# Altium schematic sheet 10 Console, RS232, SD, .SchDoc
size 420 x 297 mm; DocumentNumber: 10; SheetNumber: 10; SheetTotal: 12
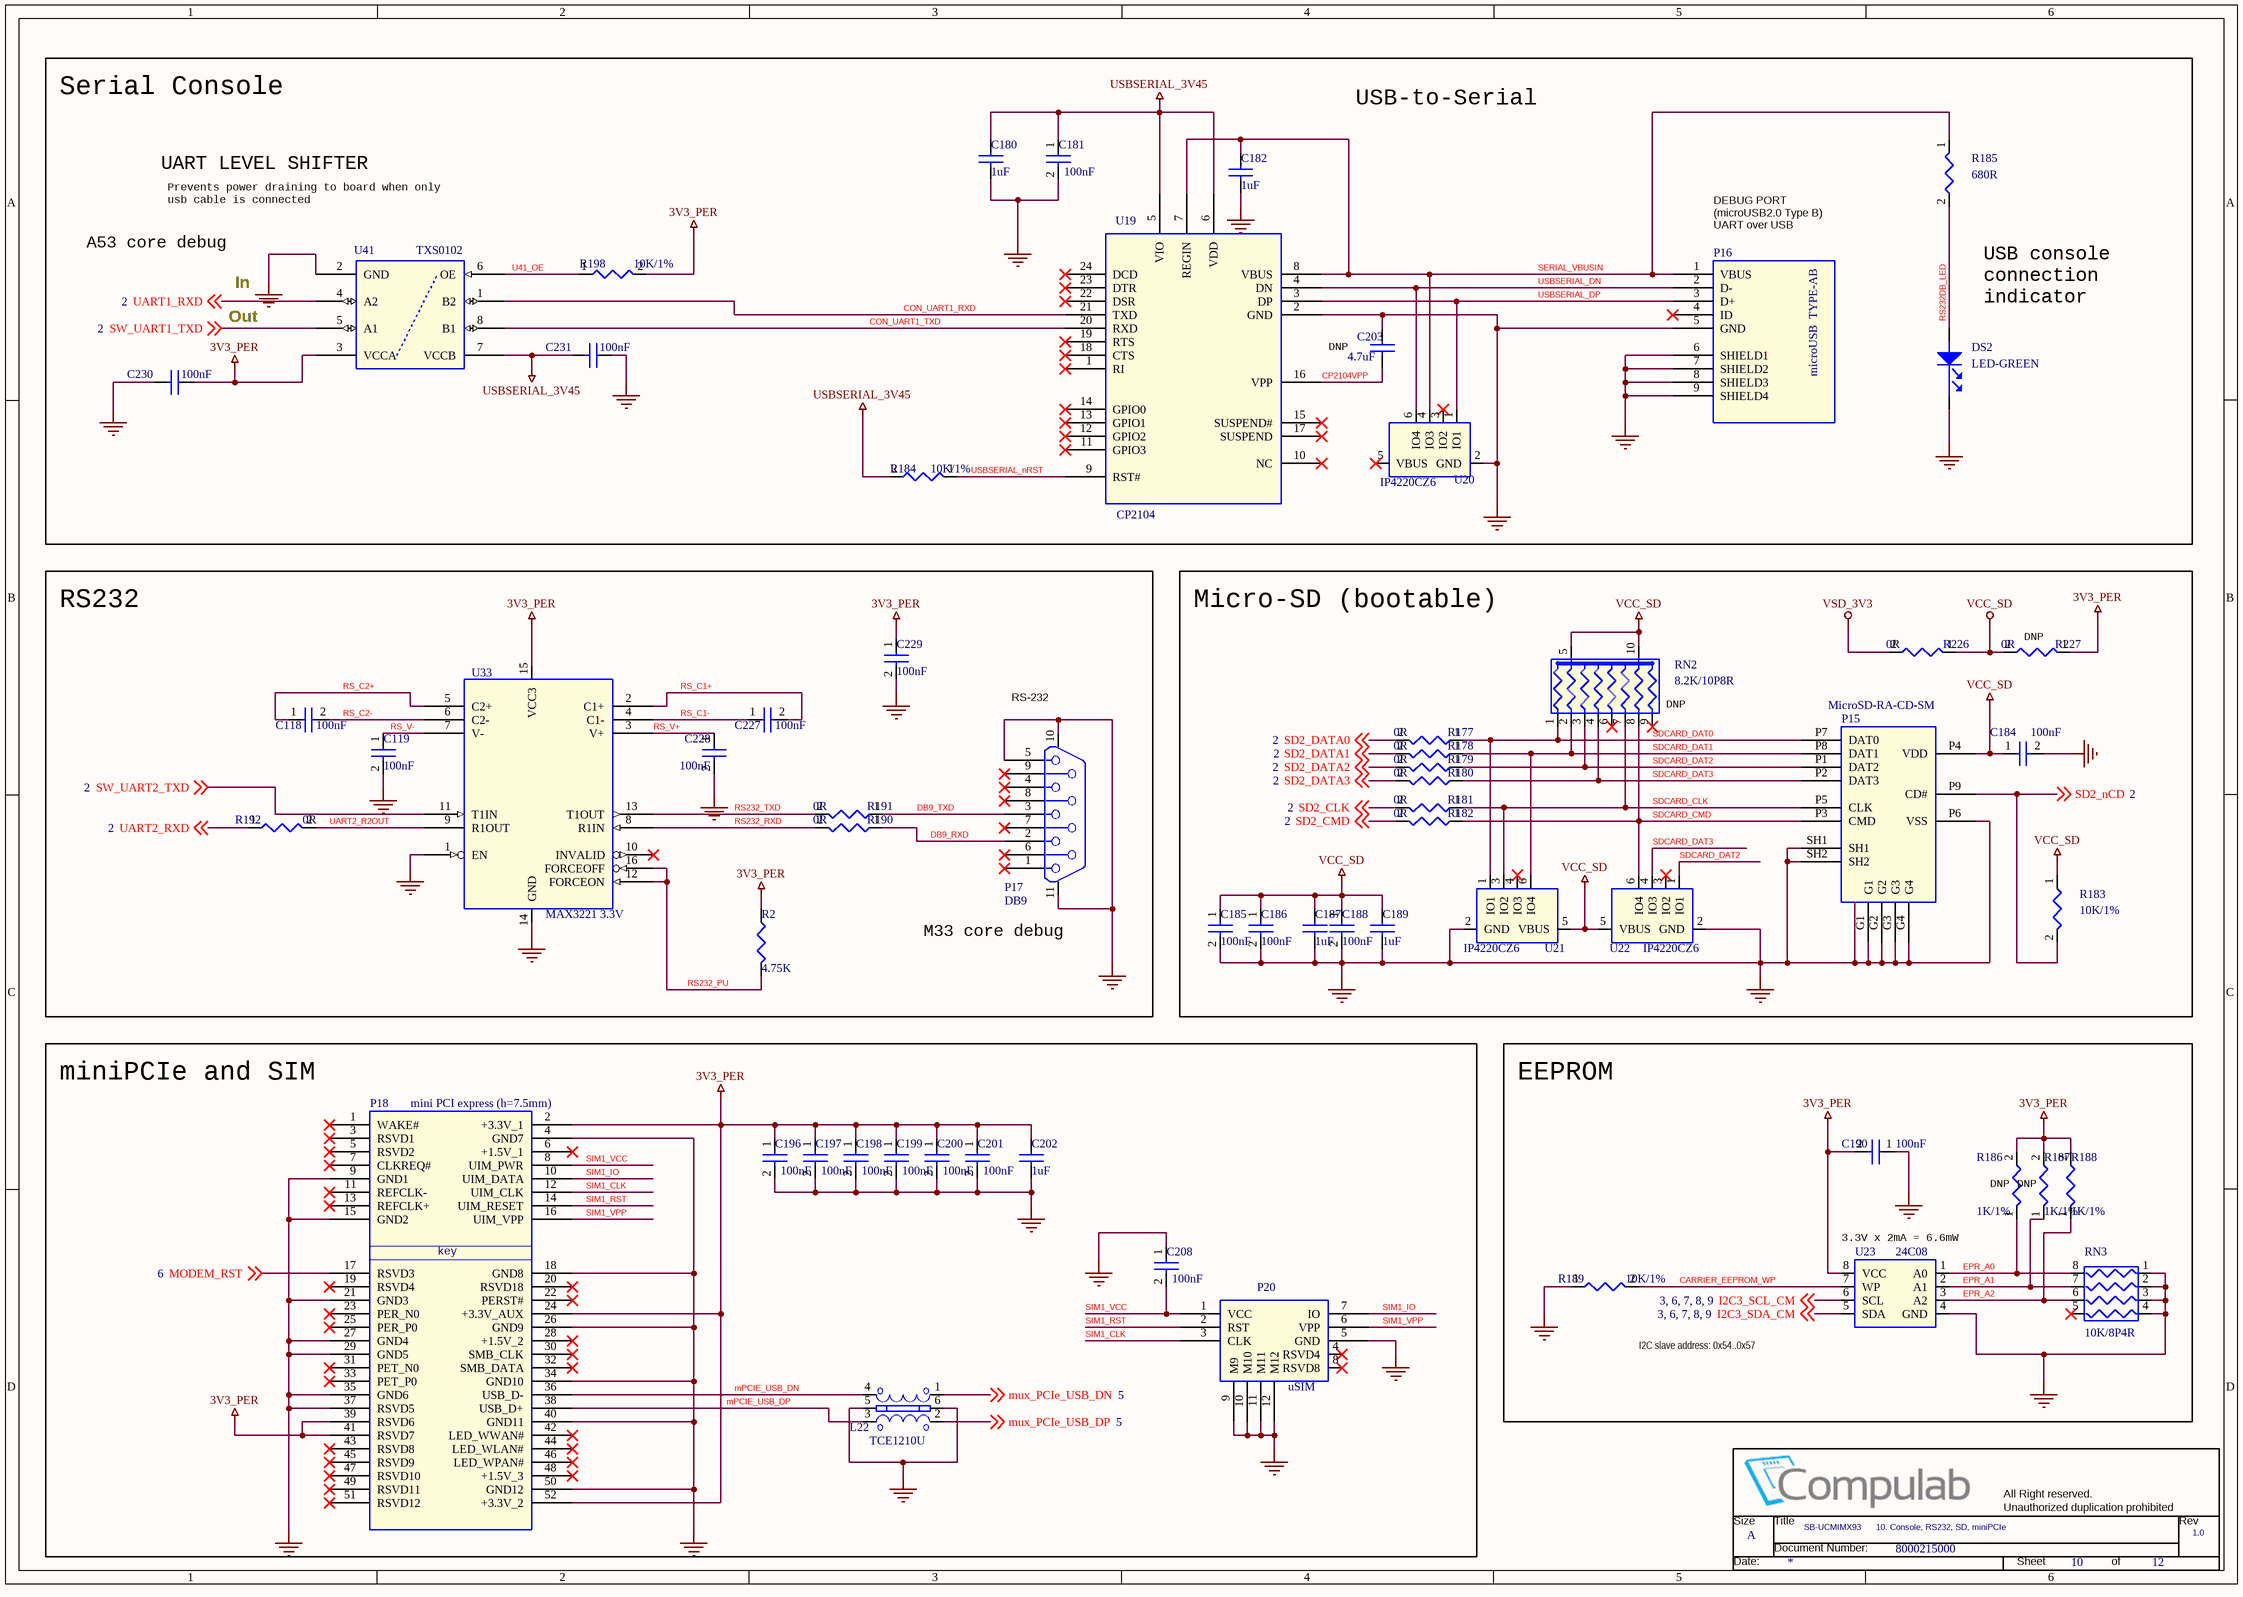
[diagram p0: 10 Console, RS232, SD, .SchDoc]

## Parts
*  Title: SB-UCMIMX93      10. Console, RS232, SD, miniPCIe  Doc: 8000215000  RevCode: 1.0  Page Size: A  Page Number: 10  Page Count: 12  (hidden comment: CompuLabTitleBlk)  (graphical)
C118  100nF  [RC0402]
C119  100nF  [RC0402]
C180  1uF  [RC0402]
C181  100nF  [RC0402]
C182  1uF  [RC0402]
C184  100nF  [RC0402]
C185  100nF  [RC0402]
C186  100nF  [RC0402]
C187  1uF  [RC0402]
C188  100nF  [RC0402]
C189  1uF  [RC0402]
C190  100nF  [RC0402]
C196  100nF  [RC0402]
C197  100nF  [RC0402]
C198  100nF  [RC0402]
C199  100nF  [RC0402]
C200  100nF  [RC0402]
C201  100nF  [RC0402]
C202  1uF  [RC0402]
C203  4.7uF  [C0603-08]
C208  100nF  [RC0402]
C227  100nF  [RC0402]
C228  100nF  [RC0402]
C229  100nF  [RC0402]
C230  100nF  [RC0402]
C231  100nF  [RC0402]
DS2  LED-GREEN  [LED-1206]
L22  TCE1210U  [EMI1012-ESD]
P15  MicroSD-RA-CD-SM  [MicroSD-RA-CD-SM]
P16  microUSB  TYPE-AB  [MICRO-USB-AB-RA-SM]
P17  DB9  [DB9RATH]
P18  mini PCI express (h=7.5mm)  [MINIPCIE-4]
P20  uSIM  [SKT-MicroSIM6-SM]
R2  4.75K  [RC0402]
R177  0R  [RC0402]
R178  0R  [RC0402]
R179  0R  [RC0402]
R180  0R  [RC0402]
R181  0R  [RC0402]
R182  0R  [RC0402]
R183  10K/1%  [RC0402]
R184  10K/1%  [RC0402]
R185  680R  [RC0402]
R186  1K/1%  [RC0402]
R187  1K/1%  [RC0402]
R188  1K/1%  [RC0402]
R189  10K/1%  [RC0402]
R190  0R  [RC0402]
R191  0R  [RC0402]
R192  0R  [RC0402]
R198  10K/1%  [RC0402]
R226  0R  [RC0402]
R227  0R  [RC0402]
RN2  8.2K/10P8R  [RESNET10P1206]
RN3  10K/8P4R  [RESNET8P0805]
U19  CP2104  [MO-220VGGD-8]
U20  IP4220CZ6  [SOT23-6L-H1]
U21  IP4220CZ6  [SOT23-6L]
U22  IP4220CZ6  [SOT23-6L]
U23  24C08  [MO-229VCED-2]
U33  MAX3221 3.3V  [SSOP-16]
U41  TXS0102  [MO-187DA-8]

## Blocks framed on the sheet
Serial Console: C180-C182 C203 C230 C231 DS2 P16 R184 R185 R198 U19 U20 U41
RS232: C118 C119 C227-C229 P17 R2 R190-R192 U33
Micro-SD (bootable): C184-C189 P15 R177-R183 R226 R227 RN2 U21 U22
miniPCIe and SIM: C196-C202 C208 L22 P18 P20
EEPROM: C190 R186-R189 RN3 U23

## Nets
3V3_PER: C190.2 C196.1 C197.1 C198.1 C199.1 C200.1 C201.1 C202.1 C229.1 C230.1 P18.2(+3.3V_1) P18.24(+3.3V_AUX) P18.39(RSVD6) P18.41(RSVD7) P18.52(+3.3V_2) R2.1 R186.2 R187.2 R188.2 R198.2 R227.1 U23.8(VCC) U33.15(VCC3) U41.3(VCCA)
GND: C119.2 C180.2 C181.2 C182.2 C184.2 C185.2 C186.2 C187.2 C188.2 C189.2 C190.1 C196.2 C197.2 C198.2 C199.2 C200.2 C201.2 C202.2 C203.2 C208.1 C228.2 C229.2 C230.2 C231.1 DS2.CATHODE L22.5(GND) L22.6(GND) P15.G1 P15.G2 P15.G3 P15.G4 P15.P6(VSS) P15.SH1 P15.SH2 P16.5(GND) P16.6(SHIELD1) P16.7(SHIELD2) P16.8(SHIELD3) P16.9(SHIELD4) P17.5 P17.10(BRACKET) P17.11(BRACKET) P18.4(GND7) P18.9(GND1) P18.15(GND2) P18.18(GND8) P18.21(GND3) P18.26(GND9) P18.27(GND4) P18.29(GND5) P18.34(GND10) P18.35(GND6) P18.37(RSVD5) P18.40(GND11) P18.50(GND12) P20.5(GND) P20.9(M9) P20.10(M10) P20.11(M11) P20.12(M12) R189.1 RN3.1(RA1) RN3.2(RB1) RN3.3(RC1) RN3.4(RD1) U19.2(GND) U20.2(GND) U21.2(GND) U22.2(GND) U23.4(GND) U33.1(EN) U33.14(GND) U41.2(GND)
USBSERIAL_3V45: C180.1 C181.1 C231.2 R184.2 U19.5(VIO) U19.6(VDD) U41.7(VCCB)
VCC_SD: C184.1 C185.1 C186.1 C187.1 C188.1 C189.1 P15.P4(VDD) R183.1 R226.1 R227.2 RN2.5(COM1) RN2.10(COM2) U21.5(VBUS) U22.5(VBUS)
VSD_3V3: R226.2
CARRIER_EEPROM_WP: R189.2 U23.7(WP)
CON_UART1_RXD: U19.21(TXD) U41.1(B2)
CON_UART1_TXD: U19.20(RXD) U41.8(B1)
CP2104VPP: C203.1 U19.16(VPP)
DB9_RXD: P17.2 R190.1
DB9_TXD: P17.3 R191.1
EPR_A0: R186.1 RN3.8(RA2) U23.1(A0)
EPR_A1: R187.1 RN3.7(RB2) U23.2(A1)
EPR_A2: R188.1 RN3.6(RC2) U23.3(A2)
I2C3_SCL_CM: U23.6(SCL) ; off-sheet I2C3_SCL_CM
I2C3_SDA_CM: U23.5(SDA) ; off-sheet I2C3_SDA_CM
MODEM_RST: P18.17(RSVD3) ; off-sheet MODEM_RST
mPCIE_USB_DN: L22.4 P18.36(USB_D-)
mPCIE_USB_DP: L22.3 P18.38(USB_D+)
mux_PCIe_USB_DN: L22.1 ; off-sheet mux_PCIe_USB_DN
mux_PCIe_USB_DP: L22.2 ; off-sheet mux_PCIe_USB_DP
RS232_PU: R2.2 U33.12(FORCEON) U33.16(FORCEOFF)
RS232_RXD: R190.2 U33.8(R1IN)
RS232_TXD: R191.2 U33.13(T1OUT)
RS232DB_LED: DS2.ANODE R185.2
RS_C1+: C227.2 U33.2(C1+)
RS_C1-: C227.1 U33.4(C1-)
RS_C2+: C118.1 U33.5(C2+)
RS_C2-: C118.2 U33.6(C2-)
RS_V+: C228.1 U33.3(V+)
RS_V-: C119.1 U33.7(V-)
SD2_CLK: R181.2 ; off-sheet SD2_CLK
SD2_CMD: R182.2 ; off-sheet SD2_CMD
SD2_DATA0: R177.2 ; off-sheet SD2_DATA0
SD2_DATA1: R178.2 ; off-sheet SD2_DATA1
SD2_DATA2: R179.2 ; off-sheet SD2_DATA2
SD2_DATA3: R180.2 ; off-sheet SD2_DATA3
SD2_nCD: P15.P9(CD#) R183.2 ; off-sheet SD2_nCD
SDCARD_CLK: P15.P5(CLK) R181.1 RN2.7(R6) U21.3(IO2)
SDCARD_CMD: P15.P3(CMD) R182.1 RN2.8(R7) U22.6(IO4)
SDCARD_DAT0: P15.P7(DAT0) R177.1 RN2.1(R1) U21.1(IO1)
SDCARD_DAT1: P15.P8(DAT1) R178.1 RN2.2(R2) U21.6(IO4)
SDCARD_DAT2: P15.P1(DAT2) R179.1 RN2.3(R3) U22.1(IO1)
SDCARD_DAT3: P15.P2(DAT3) R180.1 RN2.4(R4) U22.4(IO3)
SERIAL_VBUSIN: C182.1 P16.1(VBUS) R185.1 U19.7(REGIN) U19.8(VBUS) U20.4(IO3)
SIM1_CLK: P18.12(UIM_CLK) P20.3(CLK)
SIM1_IO: P18.10(UIM_DATA) P20.7(IO)
SIM1_RST: P18.14(UIM_RESET) P20.2(RST)
SIM1_VCC: C208.2 P18.8(UIM_PWR) P20.1(VCC)
SIM1_VPP: P18.16(UIM_VPP) P20.6(VPP)
SW_UART1_TXD: U41.5(A1) ; off-sheet SW_UART1_TXD
SW_UART2_TXD: U33.11(T1IN) ; off-sheet SW_UART2_TXD
U41_OE: R198.1 U41.6(OE)
UART1_RXD: U41.4(A2) ; off-sheet UART1_RXD
UART2_R2OUT: R192.2 U33.9(R1OUT)
UART2_RXD: R192.1 ; off-sheet UART2_RXD
USBSERIAL_DN: P16.2(D-) U19.4(DN) U20.6(IO4)
USBSERIAL_DP: P16.3(D+) U19.3(DP) U20.1(IO1)
USBSERIAL_nRST: R184.1 U19.9(RST#)

Not connected (* = marked no-connect by the designer): P16 4(ID)*; P17 1* 4* 6* 7* 8* 9*; P18 1(WAKE#)* 3(RSVD1)* 5(RSVD2)* 6(+1.5V_1)* 7(CLKREQ#)* 11(REFCLK-)* 13(REFCLK+)* 19(RSVD4)* 20(RSVD18)* 22(PERST#)* 23(PER_N0)* 25(PER_P0)* 28(+1.5V_2)* 30(SMB_CLK)* 31(PET_N0)* 32(SMB_DATA)* 33(PET_P0)* 42(LED_WWAN#)* 43(RSVD8)* 44(LED_WLAN#)* 45(RSVD9)* 46(LED_WPAN#)* 47(RSVD10)* 48(+1.5V_3)* 49(RSVD11)* 51(RSVD12)*; P20 4(RSVD4)* 8(RSVD8)*; RN2 6(R5)* 9(R8)*; RN3 5(RD2)*; U19 1(RI)* 10(NC)* 11(GPIO3)* 12(GPIO2)* 13(GPIO1)* 14(GPIO0)* 15(SUSPEND#)* 17(SUSPEND)* 18(CTS)* 19(RTS)* 22(DSR)* 23(DTR)* 24(DCD)*; U20 3(IO2)* 5(VBUS)*; U21 4(IO3)*; U22 3(IO2)*; U33 10(INVALID)*

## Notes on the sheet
- USB-to-Serial
- UART LEVEL SHIFTER
- A53 core debug
- Prevents power draining to board when only
  usb cable is connected
- (near P16) DEBUG PORT
  (microUSB2.0 Type B)
  UART over USB
- Out
- In
- USB console
  connection
  indicator
- DNP
- (near R227) DNP
- (near P17) RS-232
- (near RN2) DNP
- (near P17) M33 core debug
- (near R186) DNP
- (near U23) 3.3V x 2mA = 6.6mW
- I2C slave address: 0x54..0x57

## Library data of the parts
C118 C119 C181 C184-C186 C188 C190 C196-C201 C208 C227-C229 = 100nF, 10V, X7R, 10%, 0402_Dup1: P/N: 151B10400S
C180 C182 C187 C189 C202 = 1uF,X5R,6.3V,0402: P/N: 151B10500S
C203 = 4.7uF, 6.3V, X5R, 20%, 0603: P/N: 151B10610S; CLABCONF0: DNP
C230 C231 = 100nF, 10V, X7R, 10%, 0402_0: P/N: 151B10400S
DS2 = LED-GREEN 1206_2: P/N: 139A10020S
L22 = ESD_CHOKE_DIFFx2_10: P/N: 142D11801S
P15 = microSD_push-pull: P/N: 182K01300S
P16 = Conn., Micro-USB, B-Type: P/N: 180K00501S
P17 = DB9 RA TH Male ATX: P/N: 180K00901
P18 = mini PCIe_0: P/N: 182K05202S
P20 = uSIM SOCKET_0: P/N: 190I00601S
R2 = 10K,1%,0402,1/16W_0: P/N: 161C47511S; Group: Always
R177-R182 R190 R191 = 0R, 0402_1: P/N: 161C00005S
R183 = 10K,1%,0402,1/16W_0_Dup1: P/N: 161C10021S
R184 R189 R198 = 10K,1%,0402,1/16W: P/N: 161C10021S
R185 = 47K, 0402: P/N: 161C68001S
R186 = 1K,1%,0402,1/16W: P/N: 161C10011S; Group: CAN; CLABCONF0: DNP
R187 = 1K,1%,0402,1/16W: P/N: 161C10011S; CLABCONF0: DNP; Group: CAN
R188 = 1K,1%,0402,1/16W: P/N: 161C10011S; Group: CAN
R192 = 0R, 0402: P/N: 161C00005S
R226 = 0R, 0402_0: P/N: 161C00005S
R227 = 0R, 0402_0: P/N: 161C00005S; CLABCONF0: DNP
RN2 = RN,8.2K,10P8R@1206: P/N: 163I08822S; CLABCONF0: DNP
RN3 = RN,10K,8P4R@0805: P/N: 163K04103S
U19 = CP2104_0: P/N: 116A00140S
U20-U22 = IP4220CZ6_0: P/N: 132D42200S
U23 = 24C02, serial EE, 2KB, I2C: P/N: 111S31000S
U33 = MAX3221 RS-232 1T1R 3_2.3V XCVR: P/N: 116A32210I
U41 = TXS0102_0: P/N: 116A01020S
